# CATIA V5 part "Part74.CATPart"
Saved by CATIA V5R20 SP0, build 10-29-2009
Part number: FA 053000-2
Revision: ANY
Definition: UNKNOWN
Nomenclature: FA 053000-2
Source: Unknown
Bounding box of the stored display mesh (mm): x -1.5 to 1.5, y 0 to 3.7, z -1.5 to 1.5
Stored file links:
  C:\Users\Utente\Desktop\IO LAVORO\3D X SITO CF\CUMSA\3D files FA\FA 053004-20\Part74.CATPart

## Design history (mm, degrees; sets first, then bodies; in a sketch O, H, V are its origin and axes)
Body1 "Cortar-Extruir1" (main body)
  Solid1: solid without history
